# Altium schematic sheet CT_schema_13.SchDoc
size 147 x 119 mm
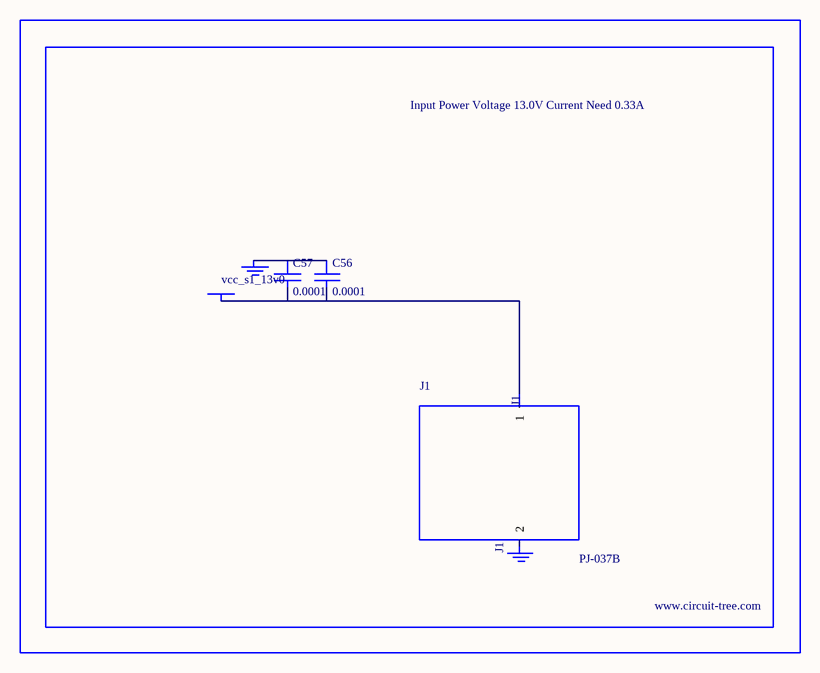
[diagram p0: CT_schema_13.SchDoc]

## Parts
BORDER12  (no value)
C56  0.0001  [EXV-9H]
C57  0.0001  [EXV-9H]
GND_INSTANCE_12_0  (no value)
GND_INSTANCE_12_1  (no value)
J1  PJ-037B  [PJ-037B_PACKAGE]
POWER_INSTANCE_12_0  vcc_s1_13v0

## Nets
NetC56_1: C56.1 C57.1 GND_INSTANCE_12_0.0(GND)
NetC56_2: C56.2 C57.2 J1.1 POWER_INSTANCE_12_0.0(PWR)

Not connected (* = marked no-connect by the designer): GND_INSTANCE_12_1 0(GND); J1 2

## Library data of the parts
BORDER12 = BORDER_PAGE12
C56 C57 = EDK107M035A9HAA
GND_INSTANCE_12_0 GND_INSTANCE_12_1 = GND
POWER_INSTANCE_12_0 = PWR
